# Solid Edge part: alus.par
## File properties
Title: alus
Author: Stella-Marii
Template: Iso Metric Part.par
Last saved by: Stella-Marii
Revision: 5
Application: Solid Edge
Density: 7833,000 kg/m^3
Accuracy: 0,990
Username: Stella-Marii
Document Number: 10
Material: Steel, structural
Face Style: Steel
Fill Style: ANSI32(Steel)
Virtual Style: Brushed steel
Grouping: Metals\Steel
LibraryName: Materials
Coef. of Thermal Exp: 1.3e-05
Thermal Conductivity: 32.0
Specific Heat: 481.0
Modulus of Elasticity: 199947953000.0
Poisson's Ratio: 0.29
Yield Stress: 262000766.0
Ultimate Stress: 358527364.0
Elongation: 0.0
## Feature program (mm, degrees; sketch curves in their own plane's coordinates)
sketch for "unnamed Protrusion 1" plane through (0, 0, 0) normal (0, 0, 1) x-axis (1, 0, 0)
  line (-350, -150) -> (350, -150)
  line (350, -150) -> (350, 150)
  line (350, 150) -> (-350, 150)
  line (-350, 150) -> (-350, -150)
  dimension (linear) = 350
  dimension (linear) = 350
extrude "unnamed Protrusion 1" add finite 117.9981 along +normal
draft "Draft_1"  Angles1 = 15 deg
fillet "Round_1" radius 40
thinwall "Thinwall_1"  Thickness = 3 mm
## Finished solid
Body 1: solid body, 35 faces, 72 edges, 40 vertices.
  Faces by surface: cylinder 16, plane 11, sphere 8
  Edges by curve: line 40, circle 24, ellipse 8
Bounding box of the edges (mm; curved faces can reach further): 700.000 x 300.000 x 117.998, from (-350, -150, 0) to (350, 150, 117.9981).
Cylindrical faces by radius (mm): R37 x8, R40 x8
Spherical faces by radius (mm): R37 x4, R40 x4
Planar faces by outward normal: +z 2, -z 1, oblique 8
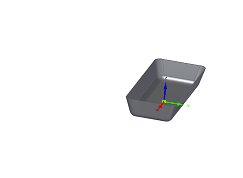
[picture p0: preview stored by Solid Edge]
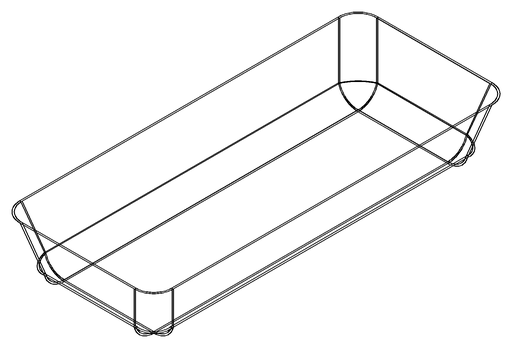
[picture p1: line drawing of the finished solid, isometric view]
